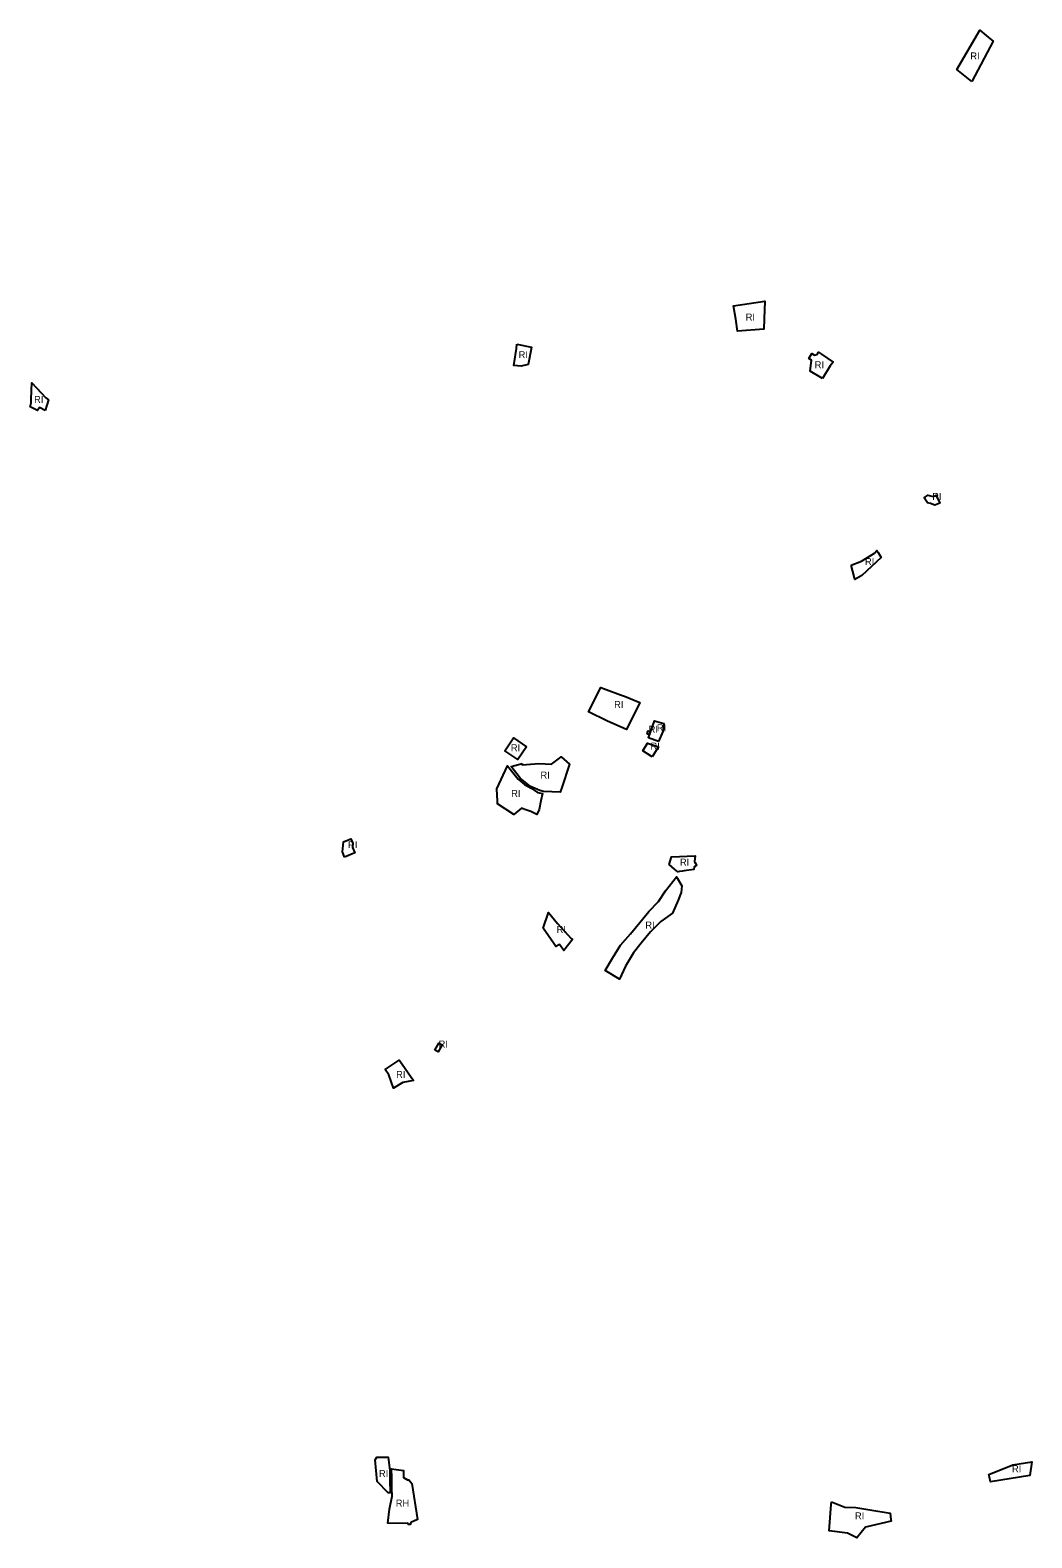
# Model space of a CAD drawing. Extents: x -477010 to -466219, y -1158799 to -1150161.
# Drawn here: x -477010 to -475715, y -1152361 to -1150412 of the extents above; entities that cross this region are included whole.
import ezdxf

# ---------------------------------------------------------------- set-up
doc = ezdxf.new("R2010")
doc.units = 0
doc.layers.add('16', color=7, linetype='Continuous')
doc.layers.add('19', color=7, linetype='Continuous')

msp = doc.modelspace()

# ---------------------------------------------------------------- linework, layer by layer
at = {"layer": '16'}
msp.add_lwpolyline([(-476524.56, -1152341.88), (-476547.52, -1152341.73), (-476545.44, -1152323.35), (-476541.99, -1152306.82), (-476542.22, -1152296.68), (-476542.11, -1152286.54), (-476542.06, -1152282.51), (-476542.58, -1152271.35), (-476527.13, -1152273.57), (-476527.053, -1152282.811), (-476522.09, -1152285.66), (-476520.36, -1152285.49), (-476516.21, -1152290.48), (-476509.01, -1152336.72), (-476517.52, -1152340.82), (-476518.73, -1152343.19), (-476521.34, -1152343.33), (-476521.42, -1152341.78)], close=True, dxfattribs=at)
at = {"layer": '19'}
for points in [[(-475792.8, -1150478.3), (-475811.82, -1150463.08), (-475782.4, -1150412.05), (-475774.09, -1150419), (-475771.49, -1150421.17), (-475765.24, -1150426.4)], [(-476097.84, -1150785.64), (-476100.55, -1150768.46), (-476060, -1150762.3), (-476060.97, -1150785.31), (-476061.52, -1150798.48), (-476095.37, -1150801.28)], [(-476380.67, -1150818.04), (-476361.801, -1150821.621), (-476362.73, -1150826.42), (-476366.17, -1150844.19), (-476375, -1150846.4), (-476384.4, -1150845.66), (-476381.3, -1150823.35)], [(-475985.77, -1150862.33), (-476001.45, -1150852.59), (-475999.78, -1150838.49), (-476003.28, -1150836.36), (-475999.33, -1150829.86), (-475995.83, -1150831.99), (-475992.59, -1150831.25), (-475990.82, -1150828.35), (-475986.72, -1150830.84), (-475971.95, -1150841.32), (-475975.93, -1150845.78)], [(-476990.2, -1150903.49), (-476997.736, -1150899.767), (-477000.03, -1150903.804), (-477009.736, -1150898.79), (-477008.47, -1150893.75), (-477008.36, -1150889.89), (-477008.03, -1150877.71), (-477007.69, -1150867.68), (-476989.27, -1150887.45), (-476985.88, -1150889.86)], [(-475842.64, -1151014.84), (-475838.84, -1151013.09), (-475837.42, -1151016.13), (-475834.12, -1151023.19), (-475840.56, -1151026.16), (-475846.23, -1151023.91), (-475850, -1151022.92), (-475854.38, -1151016.31), (-475849.58, -1151013.13)], [(-475948.71, -1151103.47), (-475935.32, -1151098.45), (-475918.38, -1151087.81), (-475915.25, -1151084.64), (-475913.64, -1151087.33), (-475909.98, -1151093.43), (-475934.93, -1151116.85), (-475943.79, -1151121.97), (-475944.31, -1151120.02)], [(-476246.89, -1151270.96), (-476241.36, -1151273.02), (-476221.85, -1151280.79), (-476238.94, -1151315.96), (-476263.52, -1151305.28), (-476288.29, -1151293.22), (-476272.3, -1151261.53), (-476265.37, -1151264.1)], [(-476212.3, -1151321.73), (-476211.34, -1151317.75), (-476208.49, -1151318.44), (-476209.45, -1151322.42)], [(-476197.45, -1151331.4), (-476210.48, -1151326.87), (-476202.84, -1151304.89), (-476190.65, -1151308.1), (-476191.88, -1151318.54)], [(-476368.37, -1151338.09), (-476379.52, -1151354.56), (-476396.12, -1151343.42), (-476384.82, -1151326.87)], [(-476205.62, -1151351.14), (-476218.06, -1151343.63), (-476211.87, -1151333.69), (-476197.68, -1151338.41)], [(-476373.74, -1151359.85), (-476374, -1151361.61), (-476357.43, -1151360.35), (-476352.27, -1151359.96), (-476336.08, -1151360.57), (-476325.53, -1151352.83), (-476323.3, -1151351.3), (-476312.68, -1151360.57), (-476322.61, -1151390.7), (-476324.71, -1151397.09), (-476346.23, -1151395.92), (-476351.16, -1151394.79), (-476362.93, -1151389.4), (-476376.2, -1151379), (-476388.16, -1151363.74)], [(-476353.92, -1151397.38), (-476347.4, -1151398.62), (-476349.48, -1151408.15), (-476351.87, -1151419.13), (-476354.92, -1151425.69), (-476362.82, -1151421.94), (-476370.34, -1151419.13), (-476374.53, -1151417.56), (-476384.58, -1151425.59), (-476405.66, -1151411.88), (-476405.83, -1151408.32), (-476406.59, -1151392.75), (-476392.86, -1151362.69), (-476378.85, -1151380.09), (-476370.78, -1151386.79), (-476362.02, -1151391.51)], [(-476603.3, -1151480.83), (-476606.21, -1151473.95), (-476604.8, -1151461.25), (-476595.09, -1151457.15), (-476592.56, -1151463.15), (-476593.03, -1151468.38), (-476590.12, -1151475.26)], [(-476164.64, -1151498.74), (-476166.57, -1151499.18), (-476170.33, -1151499.57), (-476172.47, -1151499.83), (-476176.8, -1151496.23), (-476183.89, -1151490.43), (-476180.86, -1151480.43), (-476150.27, -1151479.13), (-476150.95, -1151486.55), (-476150.47, -1151488), (-476150, -1151487.85), (-476148.69, -1151491.82), (-476150.22, -1151492.32), (-476149.98, -1151493.06), (-476151.59, -1151493.59), (-476151.85, -1151496.93)], [(-476188.38, -1151524.47), (-476174.52, -1151506.3), (-476167.41, -1151517.87), (-476168.26, -1151526.73), (-476172.39, -1151536.49), (-476179.35, -1151553.25), (-476194.74, -1151564.15), (-476207.8, -1151577.5), (-476219.85, -1151592.08), (-476230.1, -1151604.48), (-476240.26, -1151621.66), (-476248.09, -1151638.64), (-476266.39, -1151627.18), (-476257.18, -1151611.33), (-476246.52, -1151594.45), (-476233.87, -1151579.85), (-476221.58, -1151565.48), (-476209.99, -1151551.29), (-476197.76, -1151538.26)], [(-476327.96, -1151566.52), (-476310.28, -1151585.82), (-476308.93, -1151587.29), (-476320.11, -1151601.3), (-476325.52, -1151593.7), (-476330.46, -1151596.25), (-476332.97, -1151592.56), (-476346.66, -1151572.47), (-476339.71, -1151552.33)], [(-476486.59, -1151730.38), (-476481.64, -1151721.15), (-476477.12, -1151723.56), (-476482.21, -1151732.58)], [(-476546.27, -1151762.41), (-476551.036, -1151755.415), (-476532.59, -1151743.213), (-476531.81, -1151744.22), (-476514.07, -1151769.62), (-476528.19, -1151772.03), (-476540.3, -1151779.45)], [(-476563.75, -1152259.95), (-476561.473, -1152256.524), (-476546.819, -1152256.524), (-476544.75, -1152273.74), (-476544.78, -1152285.72), (-476544.61, -1152302.26), (-476547.07, -1152302.49), (-476561.32, -1152287.97)], [(-475739.46, -1152266.22), (-475715.05, -1152262.43), (-475717.71, -1152280.15), (-475768.38, -1152288.22), (-475769.74, -1152282.25), (-475770.59, -1152278.519)], [(-475974.15, -1152314.16), (-475956.68, -1152320.84), (-475942.59, -1152321.54), (-475919.32, -1152325.34), (-475903.14, -1152327.98), (-475898.12, -1152328.8), (-475897.25, -1152336.7), (-475896.97, -1152339.22), (-475930, -1152346.96), (-475941.26, -1152360.6), (-475953.51, -1152354.4), (-475976.95, -1152351.37), (-475974.4, -1152317.5)]]:
    msp.add_lwpolyline(points, close=True, dxfattribs=at)

# ---------------------------------------------------------------- texts
at = {"layer": '16'}
msp.add_text('RH', height=9, dxfattribs=at).set_placement((-476537.1885, -1152320.2671))
at = {"layer": '19'}
for p in [(-475794.5383, -1150449.8836), (-476084.8832, -1150787.3301), (-476378.4104, -1150835.9509), (-475995.6821, -1150849.0455), (-477004.6233, -1150893.8583), (-475843.821, -1151019.301), (-475930.754, -1151103.371), (-476254.917, -1151288.134), (-476210.33, -1151320.08), (-476199.855, -1151318.081), (-476388.4703, -1151344.06), (-476207.969, -1151341.837), (-476350.1386, -1151379.2642), (-476388.0163, -1151403.0603), (-476598.834, -1151469.244), (-476169.9232, -1151491.7653), (-476329.306, -1151578.721), (-476214.585, -1151573.134), (-476481.811, -1151726.876), (-476536.7228, -1151766.2596), (-476558.9272, -1152281.9965), (-475740.739, -1152275.858), (-475943.627, -1152336.715)]:
    msp.add_text('RI', height=9, dxfattribs=at).set_placement(p)

doc.saveas('drawing.dxf')
